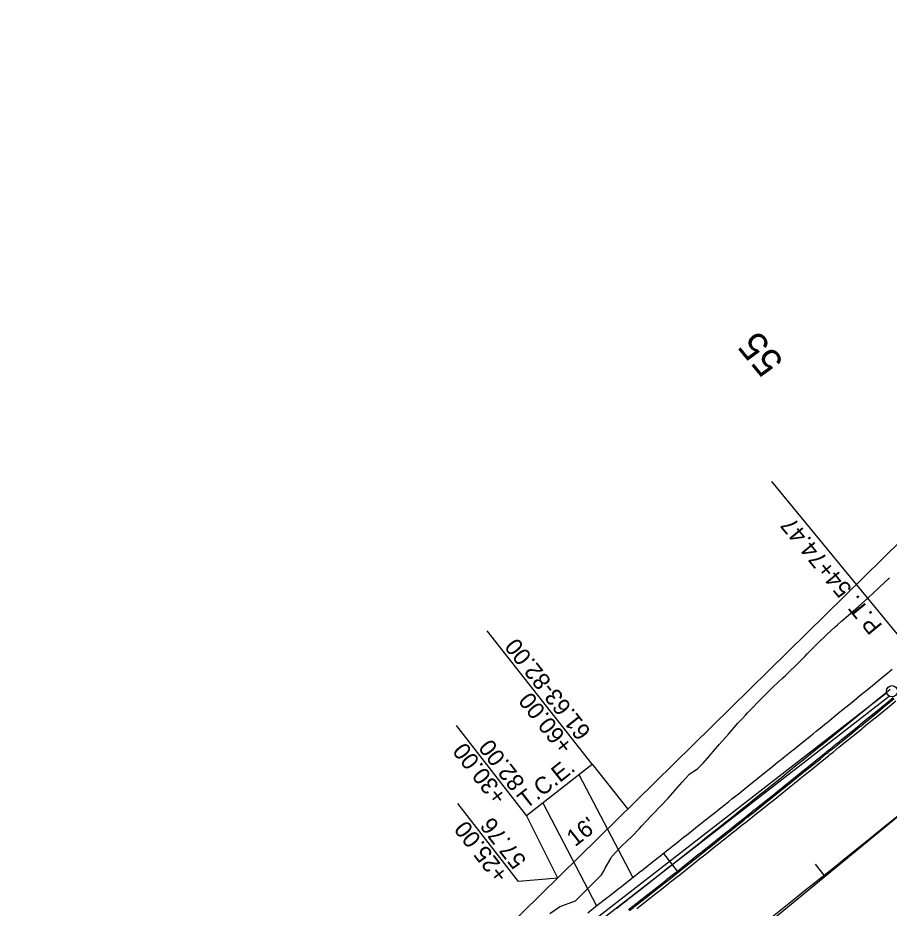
# Model space of a CAD drawing. Extents: x 1147550 to 1149124, y 2017436 to 2018779.
# Drawn here: x 1148333.9 to 1148642.9, y 2018257.9 to 2018573.6 of the extents above; entities that cross this region are included whole.
import ezdxf

# ---------------------------------------------------------------- set-up
doc = ezdxf.new("R2010")
doc.units = 0
for name, color, linetype in [('S_EDGE_CONCRETE', 7, 'Continuous'), ('S_HEADWALL', 7, 'Continuous'), ('S_IRON_PIN', 7, 'Continuous'), ('S_LANDSCAPING', 7, 'Continuous'), ('S_MAILBOX', 7, 'Continuous'), ('S_RDW_PT_SYM', 7, 'Continuous'), ('S_SECONDARY_CTL', 7, 'Continuous'), ('S_TELEPHONE_UTILITIES', 7, 'Continuous'), ('S_TELEPHONE_UTILITIES_ANNOT', 7, 'Continuous')]:
    doc.layers.add(name, color=color, linetype=linetype)

msp = doc.modelspace()

# ---------------------------------------------------------------- linework, layer by layer
at = {"layer": 'S_EDGE_CONCRETE'}
msp.add_line((1148491.47, 2018163.46), (1148677.53, 2018316.54), dxfattribs=at)
msp.add_lwpolyline([(1148616.59, 2018273.5), (1148619.71, 2018269.6)], dxfattribs=at)
msp.add_arc((1145037.29, 2022741.09), 5729.58, 304.629463, 309.445337, dxfattribs=at)
at = {"layer": 'S_HEADWALL'}
for p, q in [((1148532.88, 2018305.33), (1148551.93, 2018268.78)), ((1148520.08, 2018295.28), (1148539.11, 2018258.75)), ((1148562.81, 2018277.36), (1148567.75, 2018271.07))]:
    msp.add_line(p, q, dxfattribs=at)
at = {"layer": 'S_IRON_PIN'}
msp.add_lwpolyline([(1148525.36, 2018268.63), (1148514.33, 2018290.78), (1148537.59, 2018309.05), (1148550.22, 2018293.06)], dxfattribs=at)
at = {"layer": 'S_LANDSCAPING'}
for points in [[(1148537.59, 2018309.05), (1148500.3, 2018356.26)], [(1148514.33, 2018290.78), (1148489.4, 2018322.69)], [(1148525.36, 2018268.63), (1148511.46, 2018267.4), (1148489.94, 2018295)]]:
    msp.add_lwpolyline(points, dxfattribs=at)
at = {"layer": 'S_MAILBOX'}
msp.add_lwpolyline([(1147550.1, 2017525.89), (1147894.72, 2017801.4), (1147903.55, 2017831.14), (1148035.64, 2017933.4), (1148261.5, 2018084.85), (1148285.74, 2018084.65), (1148479.1, 2018223.18), (1148835.76, 2018573.62)], dxfattribs=at)
at = {"layer": 'S_RDW_PT_SYM'}
msp.add_lwpolyline([(1148677.53, 2018316.54), (1148601.29, 2018409.2)], dxfattribs=at)
at = {"layer": 'S_SECONDARY_CTL'}
msp.add_lwpolyline([(1148522.57, 2018256.09), (1148525.92, 2018258.43), (1148526.75, 2018258.78), (1148531.66, 2018260.55), (1148532.25, 2018261.13), (1148534.75, 2018263.62), (1148535.2, 2018264.07), (1148538.48, 2018267.37), (1148538.73, 2018267.61), (1148540.72, 2018269.62), (1148540.84, 2018269.74), (1148541.91, 2018271.58), (1148542.19, 2018272.07), (1148544.12, 2018275.53), (1148544.53, 2018276.28), (1148547.99, 2018279.89), (1148548.12, 2018280.02), (1148551.59, 2018283.33), (1148551.78, 2018283.51), (1148554.34, 2018286.21), (1148555.01, 2018286.98), (1148558.42, 2018290.65), (1148558.93, 2018291.18), (1148561.87, 2018294.24), (1148561.89, 2018294.26), (1148564.49, 2018296.97), (1148565.34, 2018297.87), (1148568.68, 2018301.63), (1148569.52, 2018302.57), (1148571.77, 2018305.18), (1148571.98, 2018305.43), (1148574.9, 2018307.34), (1148575.98, 2018308.35), (1148576.95, 2018309.4), (1148579.31, 2018312.11), (1148580.49, 2018313.48), (1148582.12, 2018315.36), (1148582.59, 2018315.94), (1148584.83, 2018318.4), (1148585.93, 2018319.68), (1148589.23, 2018323.47), (1148590.8, 2018325.2), (1148591.9, 2018326.36), (1148592.63, 2018327.14), (1148594.7, 2018329.35), (1148596.04, 2018330.78), (1148599.55, 2018334.31), (1148601.62, 2018336.25), (1148602.14, 2018336.74), (1148603.16, 2018337.71), (1148605.13, 2018339.56), (1148606.05, 2018340.43), (1148606.77, 2018341.11), (1148610.37, 2018344.52), (1148612.57, 2018346.79), (1148612.72, 2018346.95), (1148612.92, 2018347.16), (1148613.81, 2018348.12), (1148615.51, 2018349.84), (1148617.35, 2018351.6), (1148620.93, 2018355.03), (1148623.75, 2018357.73), (1148624.53, 2018358.43), (1148626.08, 2018359.78), (1148628.26, 2018361.68), (1148631.97, 2018364.95), (1148635.28, 2018367.88), (1148635.68, 2018368.23), (1148636.92, 2018369.36), (1148639.32, 2018371.68), (1148643.01, 2018375.07)], dxfattribs=at)
at = {"layer": 'S_TELEPHONE_UTILITIES'}
for points in [[(1148536, 2018256.32), (1148538.77, 2018258.47), (1148539.27, 2018258.87), (1148542.91, 2018261.71), (1148543.18, 2018261.92), (1148545.39, 2018263.66), (1148545.52, 2018263.76), (1148547.09, 2018264.98), (1148547.49, 2018265.31), (1148550.37, 2018267.56), (1148550.99, 2018268.05), (1148554.89, 2018271.12), (1148555.04, 2018271.23), (1148558.79, 2018274.19), (1148559, 2018274.35), (1148561.9, 2018276.64), (1148562.69, 2018277.26), (1148566.58, 2018280.34), (1148567.15, 2018280.79), (1148570.46, 2018283.41), (1148570.47, 2018283.42), (1148573.4, 2018285.75), (1148574.36, 2018286.51), (1148578.25, 2018289.6), (1148579.23, 2018290.38), (1148581.88, 2018292.49), (1148582.13, 2018292.69), (1148584.86, 2018294.86), (1148586.01, 2018295.78), (1148587.12, 2018296.67), (1148589.89, 2018298.88), (1148591.28, 2018300), (1148593.2, 2018301.53), (1148593.77, 2018301.98), (1148596.34, 2018304.05), (1148597.64, 2018305.09), (1148601.51, 2018308.2), (1148603.31, 2018309.65), (1148604.55, 2018310.65), (1148605.38, 2018311.31), (1148607.72, 2018313.2), (1148609.24, 2018314.43), (1148613.1, 2018317.54), (1148615.31, 2018319.33), (1148615.86, 2018319.78), (1148616.96, 2018320.67), (1148619.06, 2018322.37), (1148620.05, 2018323.17), (1148620.82, 2018323.79), (1148624.67, 2018326.92), (1148627.12, 2018328.91), (1148627.29, 2018329.05), (1148627.51, 2018329.23), (1148628.52, 2018330.05), (1148630.39, 2018331.57), (1148632.37, 2018333.19), (1148636.21, 2018336.33), (1148639.24, 2018338.8), (1148640.06, 2018339.47), (1148641.65, 2018340.77), (1148643.9, 2018342.62)], [(1148545.99, 2018257.77), (1148546.26, 2018257.99), (1148548.47, 2018259.72), (1148548.61, 2018259.82), (1148550.17, 2018261.05), (1148550.58, 2018261.37), (1148553.46, 2018263.63), (1148554.08, 2018264.12), (1148557.99, 2018267.19), (1148558.13, 2018267.3), (1148561.89, 2018270.26), (1148562.1, 2018270.43), (1148565, 2018272.72), (1148565.79, 2018273.34), (1148569.69, 2018276.42), (1148570.25, 2018276.87), (1148573.57, 2018279.49), (1148573.58, 2018279.5), (1148576.51, 2018281.83), (1148577.47, 2018282.59), (1148581.36, 2018285.68), (1148582.34, 2018286.46), (1148584.99, 2018288.58), (1148585.25, 2018288.78), (1148587.98, 2018290.95), (1148589.13, 2018291.88), (1148590.24, 2018292.76), (1148593.01, 2018294.98), (1148594.41, 2018296.09), (1148596.33, 2018297.63), (1148596.89, 2018298.08), (1148599.47, 2018300.15), (1148600.77, 2018301.19), (1148604.64, 2018304.3), (1148606.45, 2018305.75), (1148607.69, 2018306.75), (1148608.51, 2018307.42), (1148610.86, 2018309.31), (1148612.38, 2018310.53), (1148616.25, 2018313.66), (1148618.46, 2018315.45), (1148619.01, 2018315.89), (1148620.11, 2018316.78), (1148622.21, 2018318.48), (1148623.2, 2018319.28), (1148623.97, 2018319.91), (1148627.82, 2018323.04), (1148630.27, 2018325.03), (1148630.45, 2018325.17), (1148630.67, 2018325.35), (1148631.68, 2018326.18), (1148633.55, 2018327.7), (1148635.53, 2018329.31), (1148639.38, 2018332.46), (1148642.41, 2018334.93), (1148643.22, 2018335.6)], [(1148550.46, 2018257.46), (1148552.02, 2018258.69), (1148552.43, 2018259.01), (1148555.32, 2018261.27), (1148555.93, 2018261.76), (1148559.84, 2018264.83), (1148559.99, 2018264.95), (1148563.75, 2018267.91), (1148563.95, 2018268.07), (1148566.86, 2018270.36), (1148567.65, 2018270.99), (1148571.55, 2018274.07), (1148572.11, 2018274.52), (1148575.43, 2018277.14), (1148575.44, 2018277.15), (1148578.38, 2018279.48), (1148579.34, 2018280.24), (1148583.23, 2018283.34), (1148584.21, 2018284.12), (1148586.86, 2018286.23), (1148587.12, 2018286.43), (1148589.85, 2018288.61), (1148591, 2018289.53), (1148592.12, 2018290.42), (1148594.89, 2018292.63), (1148596.28, 2018293.75), (1148598.2, 2018295.29), (1148598.77, 2018295.74), (1148601.35, 2018297.81), (1148602.65, 2018298.85), (1148606.52, 2018301.96), (1148608.33, 2018303.42), (1148609.57, 2018304.41), (1148610.39, 2018305.08), (1148612.74, 2018306.97), (1148614.26, 2018308.2), (1148618.13, 2018311.32), (1148620.35, 2018313.11), (1148620.9, 2018313.56), (1148622, 2018314.45), (1148624.1, 2018316.15), (1148625.09, 2018316.95), (1148625.86, 2018317.58), (1148629.72, 2018320.71), (1148632.16, 2018322.7), (1148632.34, 2018322.85), (1148632.56, 2018323.03), (1148633.57, 2018323.85), (1148635.44, 2018325.37), (1148637.43, 2018326.99), (1148641.28, 2018330.13), (1148644.31, 2018332.61)], [(1148550.77, 2018257.07), (1148552.33, 2018258.3), (1148552.74, 2018258.62), (1148555.62, 2018260.88), (1148556.24, 2018261.36), (1148560.15, 2018264.44), (1148560.3, 2018264.55), (1148564.05, 2018267.51), (1148564.26, 2018267.68), (1148567.17, 2018269.97), (1148567.96, 2018270.59), (1148571.86, 2018273.68), (1148572.42, 2018274.12), (1148575.74, 2018276.75), (1148575.75, 2018276.76), (1148578.69, 2018279.09), (1148579.65, 2018279.85), (1148583.54, 2018282.94), (1148584.52, 2018283.72), (1148587.18, 2018285.84), (1148587.43, 2018286.04), (1148590.16, 2018288.22), (1148591.32, 2018289.14), (1148592.43, 2018290.03), (1148595.2, 2018292.24), (1148596.59, 2018293.36), (1148598.51, 2018294.9), (1148599.08, 2018295.35), (1148601.66, 2018297.42), (1148602.96, 2018298.46), (1148606.84, 2018301.57), (1148608.64, 2018303.03), (1148609.88, 2018304.02), (1148610.71, 2018304.69), (1148613.06, 2018306.58), (1148614.58, 2018307.81), (1148618.45, 2018310.93), (1148620.66, 2018312.73), (1148621.21, 2018313.17), (1148622.31, 2018314.06), (1148624.41, 2018315.77), (1148625.4, 2018316.56), (1148626.17, 2018317.19), (1148630.03, 2018320.32), (1148632.48, 2018322.32), (1148632.65, 2018322.46), (1148632.88, 2018322.64), (1148633.89, 2018323.46), (1148635.76, 2018324.98), (1148637.74, 2018326.6), (1148641.59, 2018329.75), (1148644.62, 2018332.22)], [(1148553.36, 2018257.83), (1148556.24, 2018260.09), (1148556.86, 2018260.58), (1148560.77, 2018263.65), (1148560.92, 2018263.77), (1148564.67, 2018266.73), (1148564.88, 2018266.89), (1148567.79, 2018269.18), (1148568.58, 2018269.81), (1148572.48, 2018272.89), (1148573.04, 2018273.34), (1148576.36, 2018275.97), (1148576.38, 2018275.98), (1148579.31, 2018278.3), (1148580.27, 2018279.07), (1148584.16, 2018282.16), (1148585.14, 2018282.94), (1148587.8, 2018285.06), (1148588.05, 2018285.26), (1148590.78, 2018287.44), (1148591.94, 2018288.36), (1148593.05, 2018289.25), (1148595.82, 2018291.46), (1148597.22, 2018292.58), (1148599.14, 2018294.12), (1148599.71, 2018294.57), (1148602.29, 2018296.64), (1148603.59, 2018297.68), (1148607.46, 2018300.79), (1148609.27, 2018302.25), (1148610.51, 2018303.25), (1148611.34, 2018303.91), (1148613.69, 2018305.81), (1148615.21, 2018307.03), (1148619.07, 2018310.16), (1148621.29, 2018311.95), (1148621.84, 2018312.39), (1148622.94, 2018313.28), (1148625.04, 2018314.99), (1148626.03, 2018315.79), (1148626.8, 2018316.41), (1148630.66, 2018319.55), (1148633.11, 2018321.54), (1148633.29, 2018321.68), (1148633.51, 2018321.86), (1148634.52, 2018322.69), (1148636.39, 2018324.21), (1148638.37, 2018325.83), (1148642.23, 2018328.97), (1148645.26, 2018331.45)]]:
    msp.add_lwpolyline(points, dxfattribs=at)
at = {"layer": 'S_TELEPHONE_UTILITIES_ANNOT'}
for p, q in [((1148409.31, 2018153.84), (1148641.93, 2018334.28)), ((1148409.31, 2018153.84), (1148641.93, 2018334.28)), ((1148410.23, 2018152.66), (1148642.85, 2018333.1)), ((1148410.23, 2018152.66), (1148642.85, 2018333.1))]:
    msp.add_line(p, q, dxfattribs=at)
msp.add_circle((1148643.86, 2018334.83), 2, dxfattribs=at)

# ---------------------------------------------------------------- texts
at = {"layer": 'S_HEADWALL'}
msp.add_text("16'", height=6, rotation=38.0806, dxfattribs=at).set_placement((1148531.48, 2018279.52))
at = {"layer": 'S_IRON_PIN'}
msp.add_text('T.C.E.', height=6, rotation=38.1506, dxfattribs=at).set_placement((1148514.13, 2018292.91))
at = {"layer": 'S_LANDSCAPING'}
for s, rotation, p in [('61.63-82.00', 128.3006, (1148537.4, 2018320.58)), ('+60.00', 128.3006, (1148531.12, 2018315.62)), ('+30.00', 128.0006, (1148507.7, 2018297.65)), ('82.00', 128.0006, (1148514, 2018302.57)), ('+25.00', 127.9506, (1148508.21, 2018269.94)), ('57.76', 127.9506, (1148514.52, 2018274.86))]:
    msp.add_text(s, height=6, rotation=rotation, dxfattribs=at).set_placement(p)
at = {"layer": 'S_RDW_PT_SYM'}
for s, height, p in [('55', 10, (1148605.8, 2018451.77)), ('P.T. 54+74.47', 6, (1148640.72, 2018358.12))]:
    msp.add_text(s, height=height, rotation=129.4453, dxfattribs=at).set_placement(p)

doc.saveas('drawing.dxf')
